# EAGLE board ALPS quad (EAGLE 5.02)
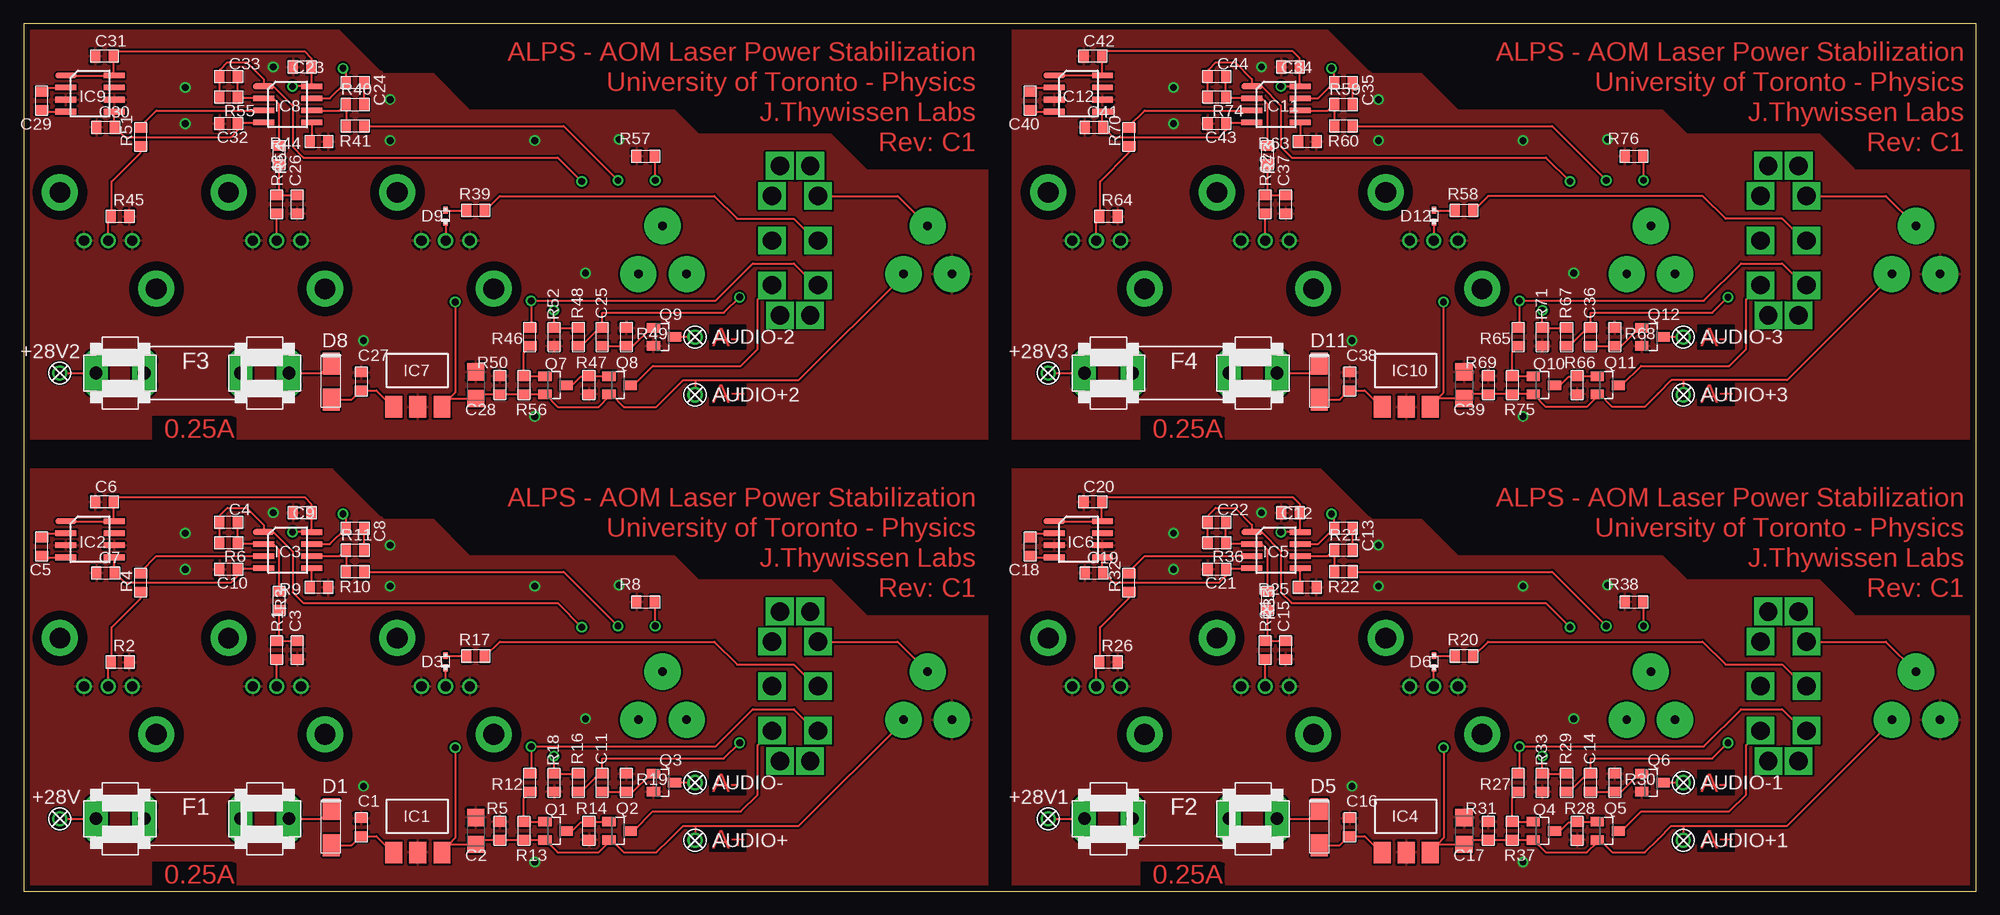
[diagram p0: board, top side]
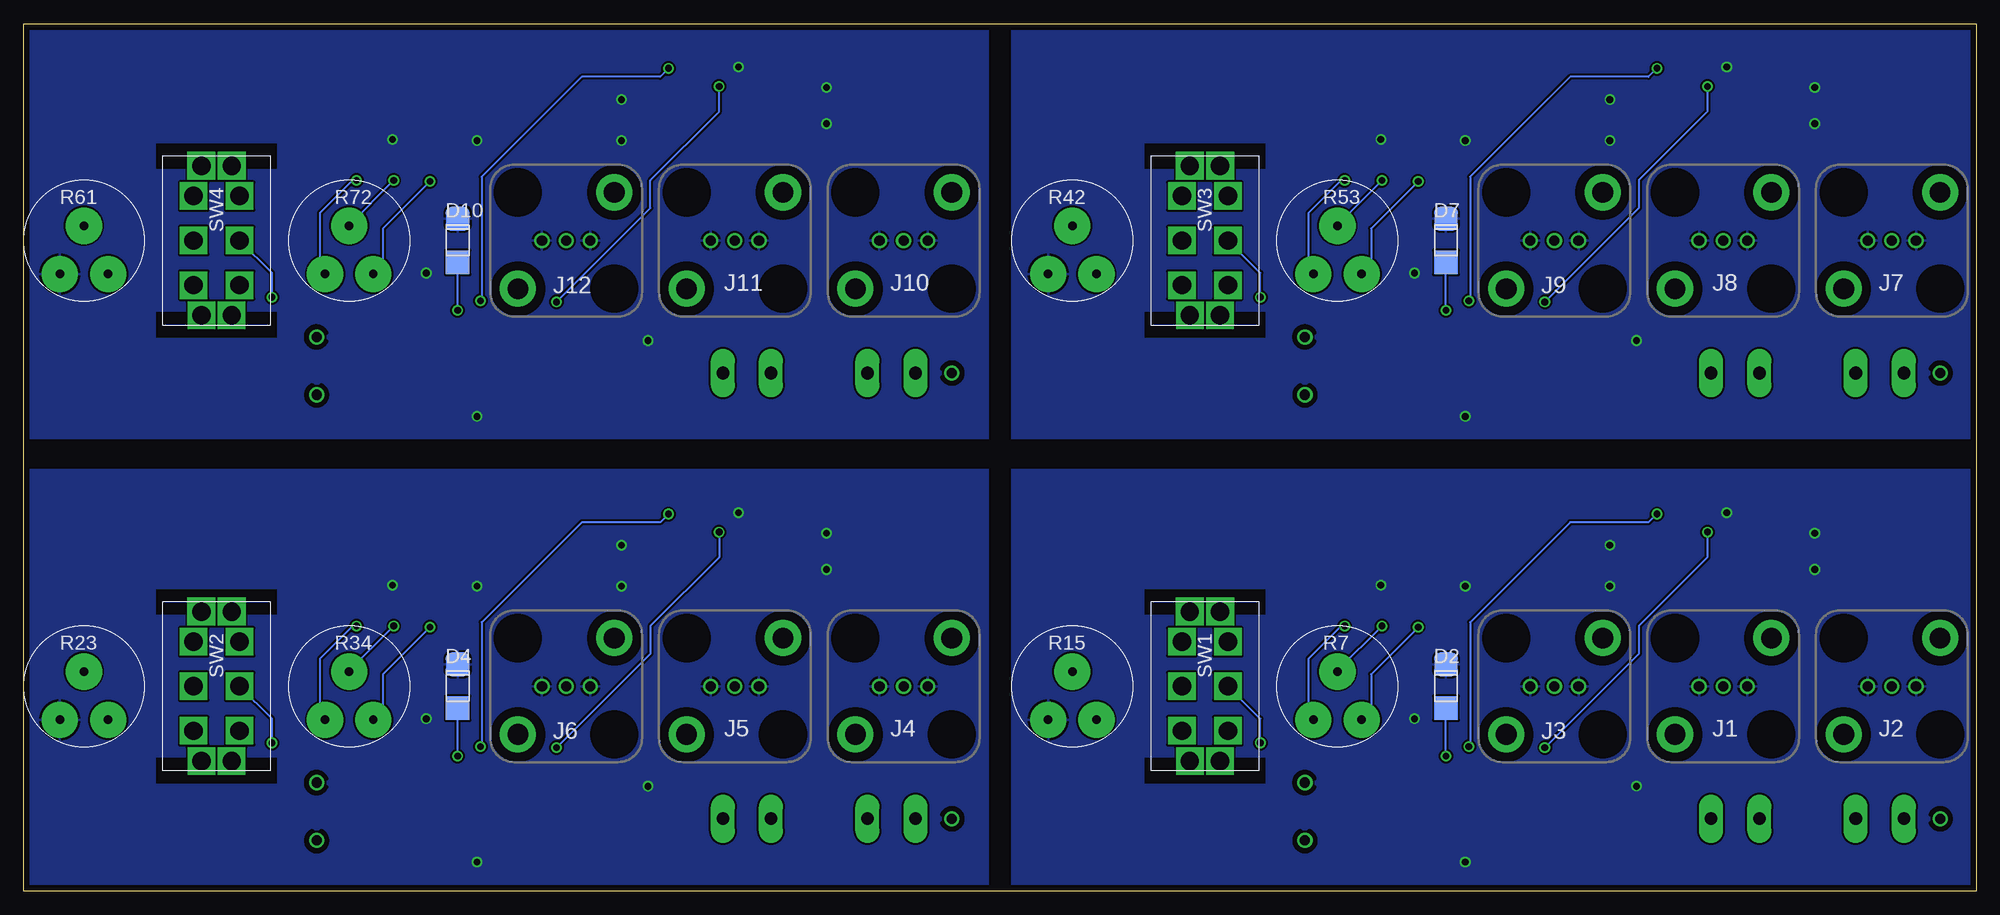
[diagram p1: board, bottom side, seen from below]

Size 205.74 x 91.44 mm. Coordinates in mm from the lower left corner, seen from the top.
Outline: 0,0 205.74,0 205.74,91.44 0,91.44 0,0
Copper layers (1*16): Top 0.035mm / dielectric 1.5mm / Bottom 0.035mm
Design rules "DRC standard check (8mil trace and gap, 20mil drill, etc) *": minimum track width 7mil, minimum drill 20mil, track to track 7mil, track to pad 7mil, pad to pad 7mil, via to via 7mil, smd to smd 7mil, copper to edge 25mil, drill to drill 8mil, minimum pad ring 10mil, minimum via ring 8mil, stop-mask expansion 4mil, vias tented up to drill 0mil, thermal gap 10mil
Net classes: 0 default: width 0.203 mm, clearance 0.203 mm
tRestrict: 73 lines
bRestrict: 1 lines

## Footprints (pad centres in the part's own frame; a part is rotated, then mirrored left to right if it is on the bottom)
TP-0.042B = drill 1.067 round: TP 0,0
2012(0805) = smd 1.016 x 1.397: 1 -0.953,0; 2 0.953,0
3216(1206) = smd 1.8 x 1.8: 1 -1.4,0; 2 1.4,0
EIA-A(SMA) = smd 2.3 x 1.8: 1A -1.905,0; 2K 1.905,0
1209 = smd 2.5 x 2.5: A 2.3,0; K -2.3,0
SOD523 = smd 0.7 x 0.5: A 0.67,0; C -0.6,0
FUSE = drill 1.321 pad 2.54 long: 1A -10.16,0; 1B -5.08,0; 2A 10.16,0; 2B 5.08,0
SOT223 = smd 1.778 x 2.286: 1 -2.54,-2.54; 2@1 0,-2.54; 3 2.54,-2.54
SOIC-8 = smd 0.6 x 2.2: 1 -1.27,-2.54; 2 0,-2.54; 3 1.27,-2.54; 4 2.54,-2.54; 5 2.54,2.54; 6 1.27,2.54; 7 0,2.54; 8 -1.27,2.54
CONN-BNC-AMP-TYPE1VERT = drill 1.067 round: CONDUCTOR 0,0; SHIELD1 -2.54,0; SHIELD2 2.54,0 | drill 2.184 pad 3.81 round: MTG1 -5.08,-5.08; MTG2 5.08,5.08
SOT23 = smd 1 x 1.4: 1 -0.953,-0.953; 2 0.953,-0.953; 3 0,1.27
PRECISION-SPR-RV8(POT) = drill 0.889 pad 3.81 round: CCW -2.54,-3.531; CW 2.54,-3.531; W 0,1.549
SWITCH-ESWITCH_100DP?VS2 = drill 1.93 square: C1 -2.42,0; C2 2.42,0; MTG3 1.595,-7.875; MTG4 -1.595,-7.875; NC1 -2.42,-4.7; NC2 2.42,-4.7; NO1 -2.42,4.7; NO2 2.42,4.7 | drill 1.93 pad 2.946 square: MTG1 -1.595,7.875; MTG2 1.595,7.875

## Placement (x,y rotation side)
+28V  Keystone 5002  [TP-0.042B]  3.81,7.62 180 top
+28V1  Keystone 5002  [TP-0.042B]  107.95,7.62 180 top
+28V2  Keystone 5002  [TP-0.042B]  3.81,54.61 180 top
+28V3  Keystone 5002  [TP-0.042B]  107.95,54.61 180 top
AUD  "Unlocked"  [MISC]  not placed on the board
AUDIO+  Keystone 5002  [TP-0.042B]  70.74,5.33 270 top
AUDIO+1  Keystone 5002  [TP-0.042B]  174.88,5.33 270 top
AUDIO+2  Keystone 5002  [TP-0.042B]  70.74,52.32 270 top
AUDIO+3  Keystone 5002  [TP-0.042B]  174.88,52.32 270 top
AUDIO-  Keystone 5002  [TP-0.042B]  70.74,11.43 0 top
AUDIO-1  Keystone 5002  [TP-0.042B]  174.88,11.43 0 top
AUDIO-2  Keystone 5002  [TP-0.042B]  70.74,58.42 0 top
AUDIO-3  Keystone 5002  [TP-0.042B]  174.88,58.42 0 top
C1  0.1uF  [2012(0805)]  35.56,6.73 270 top
C2  10uF  [3216(1206)]  47.62,6.35 270 top
C3  2.2nF  [2012(0805)]  28.83,25.4 90 top
C4  100pF  [2012(0805)]  21.59,38.86 180 top
C5  10uF  [2012(0805)]  1.91,36.32 90 top
C6  0.1uF  [2012(0805)]  8.51,41.02 180 top
C7  10uF  [2012(0805)]  8.64,33.53 0 top
C8  100pF  [2012(0805)]  34.92,38.23 180 top
C9  0.1uF  [2012(0805)]  29.34,39.88 180 top
C10  0.1uF  [2012(0805)]  21.59,33.91 180 top
C11  3.3uF  [2012(0805)]  60.96,11.43 90 top
C12  0.1uF  [2012(0805)]  133.48,39.88 180 top
C13  100pF  [2012(0805)]  139.06,38.23 180 top
C14  3.3uF  [2012(0805)]  165.1,11.43 90 top
C15  2.2nF  [2012(0805)]  132.97,25.4 90 top
C16  0.1uF  [2012(0805)]  139.7,6.73 270 top
C17  10uF  [3216(1206)]  151.76,6.35 270 top
C18  10uF  [2012(0805)]  106.05,36.32 90 top
C19  10uF  [2012(0805)]  112.78,33.53 0 top
C20  0.1uF  [2012(0805)]  112.65,41.02 180 top
C21  0.1uF  [2012(0805)]  125.73,33.91 180 top
C22  100pF  [2012(0805)]  125.73,38.86 180 top
C23  0.1uF  [2012(0805)]  29.34,86.87 180 top
C24  100pF  [2012(0805)]  34.92,85.22 180 top
C25  3.3uF  [2012(0805)]  60.96,58.42 90 top
C26  2.2nF  [2012(0805)]  28.83,72.39 90 top
C27  0.1uF  [2012(0805)]  35.56,53.72 270 top
C28  10uF  [3216(1206)]  47.62,53.34 270 top
C29  10uF  [2012(0805)]  1.91,83.31 90 top
C30  10uF  [2012(0805)]  8.64,80.52 0 top
C31  0.1uF  [2012(0805)]  8.51,88.01 180 top
C32  0.1uF  [2012(0805)]  21.59,80.9 180 top
C33  100pF  [2012(0805)]  21.59,85.85 180 top
C34  0.1uF  [2012(0805)]  133.48,86.87 180 top
C35  100pF  [2012(0805)]  139.06,85.22 180 top
C36  3.3uF  [2012(0805)]  165.1,58.42 90 top
C37  2.2nF  [2012(0805)]  132.97,72.39 90 top
C38  0.1uF  [2012(0805)]  139.7,53.72 270 top
C39  10uF  [3216(1206)]  151.76,53.34 270 top
C40  10uF  [2012(0805)]  106.05,83.31 90 top
C41  10uF  [2012(0805)]  112.78,80.52 0 top
C42  0.1uF  [2012(0805)]  112.65,88.01 180 top
C43  0.1uF  [2012(0805)]  125.73,80.9 180 top
C44  100pF  [2012(0805)]  125.73,85.85 180 top
CASE1  1590CFL  [MISC]  not placed on the board
D1  SMAZ16-13-F  [EIA-A(SMA)]  32.38,6.73 90 top
D2  Red  [1209]  55.88,21.59 270 bottom
D3  ZHCS350TA  [SOD523]  44.45,24.13 90 top
D4  Red  [1209]  160.02,21.59 270 bottom
D5  SMAZ16-13-F  [EIA-A(SMA)]  136.53,6.73 90 top
D6  ZHCS350TA  [SOD523]  148.59,24.13 90 top
D7  Red  [1209]  55.88,68.58 270 bottom
D8  SMAZ16-13-F  [EIA-A(SMA)]  32.38,53.72 90 top
D9  ZHCS350TA  [SOD523]  44.45,71.12 90 top
D10  Red  [1209]  160.02,68.58 270 bottom
D11  SMAZ16-13-F  [EIA-A(SMA)]  136.53,53.72 90 top
D12  ZHCS350TA  [SOD523]  148.59,71.12 90 top
F1  0.25A  [FUSE]  17.78,7.62 0 top
F2  0.25A  [FUSE]  121.92,7.62 0 top
F3  0.25A  [FUSE]  17.78,54.61 0 top
F4  0.25A  [FUSE]  121.92,54.61 0 top
IC1  MIC2920A-5.0WS  [SOT223]  41.53,6.6 0 top
IC2  LM2662M  [SOIC-8]  6.99,37.72 270 top
IC3  AD8032AR(z)  [SOIC-8]  27.81,36.58 270 top
IC4  MIC2920A-5.0WS  [SOT223]  145.67,6.6 0 top
IC5  AD8032AR(z)  [SOIC-8]  131.95,36.58 270 top
IC6  LM2662M  [SOIC-8]  111.12,37.72 270 top
IC7  MIC2920A-5.0WS  [SOT223]  41.53,53.59 0 top
IC8  AD8032AR(z)  [SOIC-8]  27.81,83.57 270 top
IC9  LM2662M  [SOIC-8]  6.99,84.71 270 top
IC10  MIC2920A-5.0WS  [SOT223]  145.67,53.59 0 top
IC11  AD8032AR(z)  [SOIC-8]  131.95,83.57 270 top
IC12  LM2662M  [SOIC-8]  111.12,84.71 270 top
J1  5227222-6  [CONN-BNC-AMP-TYPE1VERT]  26.67,21.59 0 bottom
J2  5227222-6  [CONN-BNC-AMP-TYPE1VERT]  8.89,21.59 0 bottom
J3  5227222-6  [CONN-BNC-AMP-TYPE1VERT]  44.45,21.59 0 bottom
J4  5227222-6  [CONN-BNC-AMP-TYPE1VERT]  113.03,21.59 0 bottom
J5  5227222-6  [CONN-BNC-AMP-TYPE1VERT]  130.81,21.59 0 bottom
J6  5227222-6  [CONN-BNC-AMP-TYPE1VERT]  148.59,21.59 0 bottom
J7  5227222-6  [CONN-BNC-AMP-TYPE1VERT]  8.89,68.58 0 bottom
J8  5227222-6  [CONN-BNC-AMP-TYPE1VERT]  26.67,68.58 0 bottom
J9  5227222-6  [CONN-BNC-AMP-TYPE1VERT]  44.45,68.58 0 bottom
J10  5227222-6  [CONN-BNC-AMP-TYPE1VERT]  113.03,68.58 0 bottom
J11  5227222-6  [CONN-BNC-AMP-TYPE1VERT]  130.81,68.58 0 bottom
J12  5227222-6  [CONN-BNC-AMP-TYPE1VERT]  148.59,68.58 0 bottom
KNOB1  OESA-50-4-6  [MISC]  not placed on the board
KNOB2  OESA-50-4-6  [MISC]  not placed on the board
LIGHTPIPE1  PLP2-500  [MISC]  not placed on the board
NUT1  1-329631-2  [MISC]  not placed on the board
NUT2  1-329631-2  [MISC]  not placed on the board
NUT3  1-329631-2  [MISC]  not placed on the board
Q1  MMBT3906  [SOT23]  55.88,6.35 270 top
Q2  MMBT3906  [SOT23]  62.61,6.35 270 top
Q3  2N7002TA  [SOT23]  67.31,11.43 270 top
Q4  MMBT3906  [SOT23]  160.02,6.35 270 top
Q5  MMBT3906  [SOT23]  166.75,6.35 270 top
Q6  2N7002TA  [SOT23]  171.45,11.43 270 top
Q7  MMBT3906  [SOT23]  55.88,53.34 270 top
Q8  MMBT3906  [SOT23]  62.61,53.34 270 top
Q9  2N7002TA  [SOT23]  67.31,58.42 270 top
Q10  MMBT3906  [SOT23]  160.02,53.34 270 top
Q11  MMBT3906  [SOT23]  166.75,53.34 270 top
Q12  2N7002TA  [SOT23]  171.45,58.42 270 top
R1  2K  [2012(0805)]  26.67,25.4 90 top
R2  49.9  [2012(0805)]  10.16,24.13 180 top
R3  1K  [2012(0805)]  26.92,30.61 90 top
R4  1K  [2012(0805)]  12.32,32.51 90 top
R5  2K  [2012(0805)]  50.16,6.35 270 top
R6  1K  [2012(0805)]  21.59,36.7 180 top
R7  1K  [PRECISION-SPR-RV8(POT)]  67.31,21.59 0 bottom
R8  49.9  [2012(0805)]  65.53,30.48 0 top
R9  1K  [2012(0805)]  31.11,32 180 top
R10  1K  [2012(0805)]  34.92,33.66 180 top
R11  0  [2012(0805)]  34.92,35.94 0 top
R12  10K  [2012(0805)]  53.34,11.43 90 top
R13  20K  [2012(0805)]  52.7,6.35 270 top
R14  10K  [2012(0805)]  59.56,6.35 90 top
R15  1K  [PRECISION-SPR-RV8(POT)]  95.25,21.59 0 bottom
R16  1K  [2012(0805)]  58.42,11.43 270 top
R17  150  [2012(0805)]  47.62,24.77 180 top
R18  10K  [2012(0805)]  55.88,11.43 90 top
R19  1M  [2012(0805)]  63.5,11.43 270 top
R20  150  [2012(0805)]  151.76,24.77 180 top
R21  0  [2012(0805)]  139.06,35.94 0 top
R22  1K  [2012(0805)]  139.06,33.66 180 top
R23  1K  [PRECISION-SPR-RV8(POT)]  199.39,21.59 0 bottom
R24  2K  [2012(0805)]  130.81,25.4 90 top
R25  1K  [2012(0805)]  135.25,32 180 top
R26  49.9  [2012(0805)]  114.3,24.13 180 top
R27  10K  [2012(0805)]  157.48,11.43 90 top
R28  10K  [2012(0805)]  163.7,6.35 90 top
R29  1K  [2012(0805)]  162.56,11.43 270 top
R30  1M  [2012(0805)]  167.64,11.43 270 top
R31  2K  [2012(0805)]  154.31,6.35 270 top
R32  1K  [2012(0805)]  116.46,32.51 90 top
R33  10K  [2012(0805)]  160.02,11.43 90 top
R34  1K  [PRECISION-SPR-RV8(POT)]  171.45,21.59 0 bottom
R35  1K  [2012(0805)]  131.06,30.61 90 top
R36  1K  [2012(0805)]  125.73,36.7 180 top
R37  20K  [2012(0805)]  156.84,6.35 270 top
R38  49.9  [2012(0805)]  169.67,30.48 0 top
R39  150  [2012(0805)]  47.62,71.75 180 top
R40  0  [2012(0805)]  34.92,82.93 0 top
R41  1K  [2012(0805)]  34.92,80.64 180 top
R42  1K  [PRECISION-SPR-RV8(POT)]  95.25,68.58 0 bottom
R43  2K  [2012(0805)]  26.67,72.39 90 top
R44  1K  [2012(0805)]  31.11,78.99 180 top
R45  49.9  [2012(0805)]  10.16,71.12 180 top
R46  10K  [2012(0805)]  53.34,58.42 90 top
R47  10K  [2012(0805)]  59.56,53.34 90 top
R48  1K  [2012(0805)]  58.42,58.42 270 top
R49  1M  [2012(0805)]  63.5,58.42 270 top
R50  2K  [2012(0805)]  50.16,53.34 270 top
R51  1K  [2012(0805)]  12.32,79.5 90 top
R52  10K  [2012(0805)]  55.88,58.42 90 top
R53  1K  [PRECISION-SPR-RV8(POT)]  67.31,68.58 0 bottom
R54  1K  [2012(0805)]  26.92,77.6 90 top
R55  1K  [2012(0805)]  21.59,83.69 180 top
R56  20K  [2012(0805)]  52.7,53.34 270 top
R57  49.9  [2012(0805)]  65.53,77.47 0 top
R58  150  [2012(0805)]  151.76,71.75 180 top
R59  0  [2012(0805)]  139.06,82.93 0 top
R60  1K  [2012(0805)]  139.06,80.64 180 top
R61  1K  [PRECISION-SPR-RV8(POT)]  199.39,68.58 0 bottom
R62  2K  [2012(0805)]  130.81,72.39 90 top
R63  1K  [2012(0805)]  135.25,78.99 180 top
R64  49.9  [2012(0805)]  114.3,71.12 180 top
R65  10K  [2012(0805)]  157.48,58.42 90 top
R66  10K  [2012(0805)]  163.7,53.34 90 top
R67  1K  [2012(0805)]  162.56,58.42 270 top
R68  1M  [2012(0805)]  167.64,58.42 270 top
R69  2K  [2012(0805)]  154.31,53.34 270 top
R70  1K  [2012(0805)]  116.46,79.5 90 top
R71  10K  [2012(0805)]  160.02,58.42 90 top
R72  1K  [PRECISION-SPR-RV8(POT)]  171.45,68.58 0 bottom
R73  1K  [2012(0805)]  131.06,77.6 90 top
R74  1K  [2012(0805)]  125.73,83.69 180 top
R75  20K  [2012(0805)]  156.84,53.34 270 top
R76  49.9  [2012(0805)]  169.67,77.47 0 top
SW1  100DP3T2B4VS2RE  [SWITCH-ESWITCH_100DP?VS2]  81.28,21.59 0 bottom
SW2  100DP3T2B4VS2RE  [SWITCH-ESWITCH_100DP?VS2]  185.42,21.59 0 bottom
SW3  100DP3T2B4VS2RE  [SWITCH-ESWITCH_100DP?VS2]  81.28,68.58 0 bottom
SW4  100DP3T2B4VS2RE  [SWITCH-ESWITCH_100DP?VS2]  185.42,68.58 0 bottom
U$18  [TITLEBLOCK_PCB]  not placed on the board
WASH1  1-329632-2  [MISC]  not placed on the board
WASH2  1-329632-2  [MISC]  not placed on the board
WASH3  1-329632-2  [MISC]  not placed on the board

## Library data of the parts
+28V +28V1-+28V3 AUDIO+ AUDIO+1-AUDIO+3 AUDIO- AUDIO-1-AUDIO-3 C1 C3 C4 C6 C8-C10 C12 C13 C15 C16 C20-C24 C26 C27 C31-C35 C37 C38 C42-C44 IC2 IC3 IC5 IC6 IC8 IC9 IC11 IC12 Q1 Q2 Q4 Q5 Q7 Q8 Q10 Q11 R1-R6 R8-R14 R16-R22 R24-R33 R35-R41 R43-R52 R54-R60 R62-R71 R73-R76 U$18 WASH1-WASH3 = QuantumOptics
AUD = QuantumOptics; MFG: Mallory; PN: MSR516WR
C2 C17 C28 C39 = QuantumOptics; MFG: Nichicon; PN: F951C106MSAAQ2
C5 C7 C18 C19 C29 C30 C40 C41 = QuantumOptics; DESC: Low ESR; MFG: AVX; PN: TCJR106M006R0500
C11 C14 C25 C36 = QuantumOptics; MFG: Yageo; PN: CC0805ZKY5V6BB335
CASE1 = QuantumOptics; MFG: Hammond
D1 D5 D8 D11 = QuantumOptics; MFG: Diodes Inc; RATING: 10V/1W
D2 D4 D7 D10 = QuantumOptics; DESC: "Unlocked"; MFG: Lumex; PN: SML-LXL1209SIC
D3 D6 D9 D12 = QuantumOptics; MFG: Zetex
F1-F4 = QuantumOptics; MFG: Littlefuse; PN: 100056
IC1 IC4 IC7 IC10 = QuantumOptics; MFG: Micrel
J1 J3 J5 J6 J8 J9 J11 J12 = QuantumOptics; DESC: "PD Input"; MFG: Amp
J2 J4 J7 J10 = QuantumOptics; DESC: "PD In"; MFG: Amp
KNOB1 KNOB2 = QuantumOptics; MFG: Kilo Int'l
LIGHTPIPE1 = QuantumOptics; MFG: Bivar inc.
NUT1-NUT3 = QuantumOptics; MFG: Amp
Q3 Q6 Q9 Q12 = QuantumOptics; MFG: Zetex; PKG: SOT23
R7 R34 R53 R72 = QuantumOptics; DESC: "Gain"; MFG: Precision Elec.; PN: SPRU1031S28
R15 R23 R42 R61 = QuantumOptics; MFG: Precision Electronics Components; PN: SPRU1021S28
SW1-SW4 = QuantumOptics; ALTPN: (Alt: 100DP1T1B1M2REH); DESC: "Man/Auto"; MFG: E-Switch

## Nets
+5V: AUDIO+.TP C2.2 C6.1 C9.1 IC1.3 IC2.1 IC2.8 IC3.8 Q1.2 Q2.2 R5.2 R13.2 R15.CW
+5V1: AUDIO+1.TP C12.1 C17.2 C20.1 IC4.3 IC5.8 IC6.1 IC6.8 Q4.2 Q5.2 R23.CW R31.2 R37.2
+5V2: AUDIO+2.TP C23.1 C28.2 C31.1 IC7.3 IC8.8 IC9.1 IC9.8 Q7.2 Q8.2 R42.CW R50.2 R56.2
+5V3: AUDIO+3.TP C34.1 C39.2 C42.1 IC10.3 IC11.8 IC12.1 IC12.8 Q10.2 Q11.2 R61.CW R69.2 R75.2
-5V: C7.2 C10.1 IC2.5 IC3.4
-5V1: C19.2 C21.1 IC5.4 IC6.5
-5V2: C30.2 C32.1 IC8.4 IC9.5
-5V3: C41.2 C43.1 IC11.4 IC12.5
AGND: C1.1 C2.1 C3.1 C6.2 C7.1 C9.2 C10.2 D2.K IC1.2@1 IC2.3 IC2.6 J1.SHIELD1 J1.SHIELD2 J2.SHIELD1 J2.SHIELD2 J3.SHIELD1 J3.SHIELD2 Q3.2 R2.1 R5.1 R8.1 R9.1 R14.1 R15.CCW R18.1 R19.1
AGND1: C12.2 C15.1 C16.1 C17.1 C19.1 C20.2 C21.2 D4.K IC4.2@1 IC6.3 IC6.6 J4.SHIELD1 J4.SHIELD2 J5.SHIELD1 J5.SHIELD2 J6.SHIELD1 J6.SHIELD2 Q6.2 R23.CCW R25.1 R26.1 R28.1 R30.1 R31.1 R33.1 R38.1
AGND2: C23.2 C26.1 C27.1 C28.1 C30.1 C31.2 C32.2 D7.K IC7.2@1 IC9.3 IC9.6 J7.SHIELD1 J7.SHIELD2 J8.SHIELD1 J8.SHIELD2 J9.SHIELD1 J9.SHIELD2 Q9.2 R42.CCW R44.1 R45.1 R47.1 R49.1 R50.1 R52.1 R57.1
AGND3: C34.2 C37.1 C38.1 C39.1 C41.1 C42.2 C43.2 D10.K IC10.2@1 IC12.3 IC12.6 J10.SHIELD1 J10.SHIELD2 J11.SHIELD1 J11.SHIELD2 J12.SHIELD1 J12.SHIELD2 Q12.2 R61.CCW R63.1 R64.1 R66.1 R68.1 R69.1 R71.1 R76.1
N$1: D3.C J3.CONDUCTOR
N$2: D6.C J6.CONDUCTOR
N$3: IC3.6 R10.2 R11.1
N$4: C8.1 R11.2
N$5: R17.1 SW1.C1
N$6: R15.W SW1.NO1
N$7: J1.CONDUCTOR R1.1
N$8: IC3.5 R9.2
N$9: Q1.3 Q2.1 R14.2
N$10: J2.CONDUCTOR R2.2 R4.1
N$11: Q1.1 R12.1 R13.1
N$12: C11.2 R16.2 SW1.C2
N$13: D2.A R16.1 R18.2
N$14: Q2.3 SW1.NC2
N$15: C11.1 Q3.1 R19.2
N$16: AUDIO-.TP Q3.3
N$17: C1.2 D1.1A IC1.1
N$18: C5.2 IC2.2
N$19: +28V.TP F1.1A
N$20: D1.2K F1.2A
N$21: C4.2 IC3.1 R6.2 R7.CW
N$22: C4.1 IC3.2 R3.2 R6.1
N$23: IC3.3 R4.2
N$24: R7.W R10.1
N$25: R7.CCW R8.2
N$26: C5.1 IC2.4
N$27: C3.2 R1.2 R3.1
N$28: D3.A R17.2
N$29: C8.2 IC3.7 R12.2 SW1.NC1
N$30: IC5.6 R21.1 R22.2
N$31: C13.1 R21.2
N$32: R20.1 SW2.C1
N$33: R23.W SW2.NO1
N$34: J5.CONDUCTOR R24.1
N$35: IC5.5 R25.2
N$36: J4.CONDUCTOR R26.2 R32.1
N$37: Q4.3 Q5.1 R28.2
N$38: Q4.1 R27.1 R37.1
N$39: C14.2 R29.2 SW2.C2
N$40: D4.A R29.1 R33.2
N$41: C14.1 Q6.1 R30.2
N$42: C16.2 D5.1A IC4.1
N$43: D5.2K F2.2A
N$44: +28V1.TP F2.1A
N$45: Q5.3 SW2.NC2
N$46: AUDIO-1.TP Q6.3
N$47: C18.2 IC6.2
N$48: C18.1 IC6.4
N$49: C15.2 R24.2 R35.1
N$50: C22.2 IC5.1 R34.CW R36.2
N$51: C22.1 IC5.2 R35.2 R36.1
N$52: D6.A R20.2
N$53: IC5.3 R32.2
N$54: R22.1 R34.W
N$55: R34.CCW R38.2
N$56: C13.2 IC5.7 R27.2 SW2.NC1
N$57: D9.C J9.CONDUCTOR
N$58: IC8.6 R40.1 R41.2
N$59: C24.1 R40.2
N$60: R39.1 SW3.C1
N$61: R42.W SW3.NO1
N$62: J8.CONDUCTOR R43.1
N$63: IC8.5 R44.2
N$64: J7.CONDUCTOR R45.2 R51.1
N$65: Q7.3 Q8.1 R47.2
N$66: Q7.1 R46.1 R56.1
N$67: C25.2 R48.2 SW3.C2
N$68: D7.A R48.1 R52.2
N$69: C25.1 Q9.1 R49.2
N$70: C27.2 D8.1A IC7.1
N$71: D8.2K F3.2A
N$72: +28V2.TP F3.1A
N$73: Q8.3 SW3.NC2
N$74: AUDIO-2.TP Q9.3
N$75: C29.2 IC9.2
N$76: C29.1 IC9.4
N$77: C26.2 R43.2 R54.1
N$78: C33.2 IC8.1 R53.CW R55.2
N$79: C33.1 IC8.2 R54.2 R55.1
N$80: D9.A R39.2
N$81: IC8.3 R51.2
N$82: R41.1 R53.W
N$83: R53.CCW R57.2
N$84: C24.2 IC8.7 R46.2 SW3.NC1
N$85: D12.C J12.CONDUCTOR
N$86: IC11.6 R59.1 R60.2
N$87: C35.1 R59.2
N$88: R58.1 SW4.C1
N$89: R61.W SW4.NO1
N$90: J11.CONDUCTOR R62.1
N$91: IC11.5 R63.2
N$92: J10.CONDUCTOR R64.2 R70.1
N$93: Q10.3 Q11.1 R66.2
N$94: Q10.1 R65.1 R75.1
N$95: C36.2 R67.2 SW4.C2
N$96: D10.A R67.1 R71.2
N$97: C36.1 Q12.1 R68.2
N$98: C38.2 D11.1A IC10.1
N$99: D11.2K F4.2A
N$100: +28V3.TP F4.1A
N$101: Q11.3 SW4.NC2
N$102: AUDIO-3.TP Q12.3
N$103: C40.2 IC12.2
N$104: C40.1 IC12.4
N$105: C37.2 R62.2 R73.1
N$106: C44.2 IC11.1 R72.CW R74.2
N$107: C44.1 IC11.2 R73.2 R74.1
N$108: D12.A R58.2
N$109: IC11.3 R70.2
N$110: R60.1 R72.W
N$111: R72.CCW R76.2
N$112: C35.2 IC11.7 R65.2 SW4.NC1

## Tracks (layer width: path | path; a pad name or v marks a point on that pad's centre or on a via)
+5V  (via drill 0.71)
  Top 0.203: IC2.1 IC2.8 9.53,38.86 9.46,38.92 C6.1 9.46,41.15 9.53,41.15 9.91,41.53 29.59,41.53 30.29,40.83 C9.1 30.29,38.16 30.35,38.1 IC3.8 v28.32,37.85 | IC1.3 44.07,4.19 44.83,4.95 | 44.83,4.95 45.47,5.59 v45.47,15.11 | R15.CW 92.71,17.91 81.66,6.86 70.74,6.86 | 70.74,6.86 AUDIO+.TP | 68.07,5.46 68.01,5.4 | 68.07,5.46 69.47,6.86 70.74,6.86 | 44.83,4.95 C2.2 48.07,5.4 R5.2 50.16,5.46 50.23,5.4 R13.2 52.7,5.46 52.77,5.4 Q1.2 54.93,5.46 54.99,5.33 56.26,4.06 60.58,4.06 61.66,5.14 Q2.2 61.91,5.4 63.25,4.06 66.67,4.06 68.07,5.46
  Bottom 0.203: v45.47,15.11 35.56,25.02 35.56,27.94 28.32,35.18 v28.32,37.85
+5V1  (via drill 0.71)
  Top 0.203: IC6.1 IC6.8 113.67,38.86 113.6,38.92 C20.1 113.6,41.15 113.67,41.15 114.05,41.53 133.73,41.53 134.43,40.83 C12.1 134.43,38.16 134.49,38.1 IC5.8 v132.46,37.85 | IC4.3 148.21,4.19 148.97,4.95 | 148.97,4.95 149.61,5.59 v149.61,15.11 | R23.CW 196.85,17.91 185.8,6.86 174.88,6.86 | 174.88,6.86 AUDIO+1.TP | 172.21,5.46 172.15,5.4 | 172.21,5.46 173.61,6.86 174.88,6.86 | 148.97,4.95 C17.2 152.21,5.4 R31.2 154.31,5.46 154.37,5.4 R37.2 156.84,5.46 156.91,5.4 Q4.2 159.07,5.46 159.13,5.33 160.4,4.06 164.72,4.06 165.8,5.14 Q5.2 166.05,5.4 167.39,4.06 170.81,4.06 172.21,5.46
  Bottom 0.203: v149.61,15.11 139.7,25.02 139.7,27.94 132.46,35.18 v132.46,37.85
+5V2  (via drill 0.71)
  Top 0.203: IC9.1 IC9.8 9.53,85.85 9.46,85.92 C31.1 9.46,88.14 9.53,88.14 9.91,88.52 29.59,88.52 30.29,87.82 C23.1 30.29,85.15 30.35,85.09 IC8.8 v28.32,84.84 | IC7.3 44.07,51.18 44.83,51.94 | 44.83,51.94 45.47,52.58 v45.47,62.1 | R42.CW 92.71,64.9 81.66,53.85 70.74,53.85 | 70.74,53.85 AUDIO+2.TP | 68.07,52.45 68.01,52.39 | 68.07,52.45 69.47,53.85 70.74,53.85 | 44.83,51.94 C28.2 48.07,52.39 R50.2 50.16,52.45 50.23,52.39 R56.2 52.7,52.45 52.77,52.39 Q7.2 54.93,52.45 54.99,52.32 56.26,51.05 60.58,51.05 61.66,52.13 Q8.2 61.91,52.39 63.25,51.05 66.67,51.05 68.07,52.45
  Bottom 0.203: v45.47,62.1 35.56,72.01 35.56,74.93 28.32,82.17 v28.32,84.84
+5V3  (via drill 0.71)
  Top 0.203: IC12.1 IC12.8 113.67,85.85 113.6,85.92 C42.1 113.6,88.14 113.67,88.14 114.05,88.52 133.73,88.52 134.43,87.82 C34.1 134.43,85.15 134.49,85.09 IC11.8 v132.46,84.84 | IC10.3 148.21,51.18 148.97,51.94 | 148.97,51.94 149.61,52.58 v149.61,62.1 | R61.CW 196.85,64.9 185.8,53.85 174.88,53.85 | 174.88,53.85 AUDIO+3.TP | 172.21,52.45 172.15,52.39 | 172.21,52.45 173.61,53.85 174.88,53.85 | 148.97,51.94 C39.2 152.21,52.39 R69.2 154.31,52.45 154.37,52.39 R75.2 156.84,52.45 156.91,52.39 Q10.2 159.07,52.45 159.13,52.32 160.4,51.05 164.72,51.05 165.8,52.13 Q11.2 166.05,52.39 167.39,51.05 170.81,51.05 172.21,52.45
  Bottom 0.203: v149.61,62.1 139.7,72.01 139.7,74.93 132.46,82.17 v132.46,84.84
-5V
  Top 0.203: IC2.5 9.53,33.66 9.59,33.66 C7.2 9.65,33.53 10.67,32.51 21.84,32.51 22.54,33.21 C10.1 22.48,33.91 22.61,34.04 IC3.4
-5V1
  Top 0.203: IC6.5 113.67,33.66 113.73,33.66 C19.2 113.79,33.53 114.81,32.51 125.98,32.51 126.68,33.21 C21.1 126.62,33.91 126.75,34.04 IC5.4
-5V2
  Top 0.203: IC9.5 9.53,80.64 9.59,80.64 C30.2 9.65,80.52 10.67,79.5 21.84,79.5 22.54,80.2 C32.1 22.48,80.9 22.61,81.03 IC8.4
-5V3
  Top 0.203: IC12.5 113.67,80.64 113.73,80.64 C41.2 113.79,80.52 114.81,79.5 125.98,79.5 126.68,80.2 C43.1 126.62,80.9 126.75,81.03 IC11.4
AGND  (via drill 0.71)
  other vias: 17.02,33.91 17.02,37.72 38.61,36.45 38.61,32.13 53.85,32.13 59.18,18.16 62.74,32.26 35.81,11.05 53.85,3.05 26.29,39.88
  pour Top: 0,0 101.6,0 101.6,29.21 88.9,29.21 85.09,33.02 71.12,33.02 68.58,35.56 46.99,35.56 43.18,39.37 37.59,39.37 32.51,44.45 0,44.45
  pour Bottom: 0,0 101.6,0 101.6,44.45 0,44.45
AGND1  (via drill 0.71)
  other vias: 121.16,33.91 121.16,37.72 142.75,36.45 142.75,32.13 157.99,32.13 163.32,18.16 166.88,32.26 139.95,11.05 157.99,3.05 130.43,39.88
  pour Top: 104.14,0 205.74,0 205.74,29.21 193.04,29.21 189.23,33.02 175.26,33.02 172.72,35.56 151.13,35.56 147.32,39.37 141.73,39.37 136.65,44.45 104.14,44.45
  pour Bottom: 104.14,0 205.74,0 205.74,44.45 104.14,44.45
AGND2  (via drill 0.71)
  other vias: 17.02,80.9 17.02,84.71 38.61,83.44 38.61,79.12 53.85,79.12 59.18,65.15 62.74,79.25 35.81,58.04 53.85,50.04 26.29,86.87
  pour Top: 0,46.99 101.6,46.99 101.6,76.2 88.9,76.2 85.09,80.01 71.12,80.01 68.58,82.55 46.99,82.55 43.18,86.36 37.59,86.36 32.51,91.44 0,91.44
  pour Bottom: 0,46.99 101.6,46.99 101.6,91.44 0,91.44
AGND3  (via drill 0.71)
  other vias: 121.16,80.9 121.16,84.71 142.75,83.44 142.75,79.12 157.99,79.12 163.32,65.15 166.88,79.25 139.95,58.04 157.99,50.04 130.43,86.87
  pour Top: 104.14,46.99 205.74,46.99 205.74,76.2 193.04,76.2 189.23,80.01 175.26,80.01 172.72,82.55 151.13,82.55 147.32,86.36 141.73,86.36 136.65,91.44 104.14,91.44
  pour Bottom: 104.14,46.99 205.74,46.99 205.74,91.44 104.14,91.44
N$1
  Top 0.203: J3.CONDUCTOR 44.58,21.59 44.45,21.72 D3.C
N$2
  Top 0.203: J6.CONDUCTOR 148.72,21.59 148.59,21.72 D6.C
N$3
  Top 0.203: R10.2 33.97,35.88 34.04,35.94 R11.1 33.91,35.94 33.27,35.31 IC3.6
N$4
  Top 0.203: R11.2 35.81,35.94 35.88,36.01 C8.1
N$5
  Top 0.203: SW1.C1 83.44,21.59 81.15,23.88 75.18,23.88 72.77,26.29 50.16,26.29 48.64,24.77 R17.1
N$6
  Top 0.203: R15.W 95.25,23.11 92.07,26.29 SW1.NO1
N$7
  Top 0.203: J1.CONDUCTOR R1.1
N$8
  Top 0.203: R9.2 30.1,31.88 30.35,32.13 IC3.5
N$9
  Top 0.203: Q1.3 57.78,6.35 58.67,7.24 59.44,7.24 59.56,7.37 | 59.56,7.37 R14.2 | Q2.1 59.63,7.3 59.56,7.37
N$10
  Top 0.203: J2.CONDUCTOR 8.89,23.75 9.27,24.13 | R4.1 12.32,30.86 9.27,27.81 9.27,24.13 | 9.27,24.13 R2.2
N$11
  Top 0.203: Q1.1 52.77,7.3 52.7,7.24 R13.1 52.7,9.78 53.34,10.41 R12.1
N$12  (via drill 0.71)
  Top 0.203: R16.2 58.74,10.48 60.2,11.94 60.45,11.94 60.96,12.45 | 60.96,12.45 C11.2 | 60.96,12.45 60.96,13.97 73.79,13.97 v75.44,15.62
  Bottom 0.203: SW1.C2 75.44,18.16 v75.44,15.62
N$13  (via drill 0.71)
  Top 0.203: R16.1 55.94,12.38 55.88,12.45 R18.2 v55.88,14.22
  Bottom 0.203: 55.88,19.3 D2.A v55.88,14.22
N$14
  Top 0.203: Q2.3 64.26,6.35 66.29,8.38 75.56,8.38 77.34,10.16 77.34,15.37 78.74,16.76 SW1.NC2
N$15
  Top 0.203: C11.1 63.44,10.48 63.5,10.54 | Q3.1 66.1,12.38 64.14,10.41 63.63,10.41 63.5,10.54 | 63.5,10.54 R19.2
N$16
  Top 0.203: AUDIO-.TP Q3.3
N$17
  Top 0.203: D1.1A 34.54,4.83 35.56,5.84 C1.2 37.15,5.78 38.99,3.94 IC1.1
N$18
  Top 0.203: C5.2 1.91,37.21 2.41,37.72 IC2.2
N$19
  Top 0.203: +28V.TP F1.1A
N$20
  Top 0.203: F1.2A 31.37,7.62 D1.2K
N$21  (via drill 0.71)
  Top 0.203: R6.2 20.64,38.8 20.7,38.86 C4.2 20.57,38.86 20.7,38.99 20.7,39.62 21.46,40.39 23.5,40.39 25.27,38.61 IC3.1 26.29,37.85 28.32,35.81 28.32,31.5 29.46,30.35 56.26,30.35 v58.8,27.81
  Bottom 0.203: R7.CW 64.77,18.16 63.75,19.18 63.75,22.86 v58.8,27.81
N$22
  Top 0.203: C4.1 22.48,38.86 22.54,38.8 R6.1 22.48,36.7 22.61,36.58 IC3.2 26.29,36.58 26.92,35.94 R3.2
N$23
  Top 0.203: R4.2 12.32,33.66 13.97,35.31 IC3.3
N$24  (via drill 0.71)
  Top 0.203: R10.1 56.9,33.66 v62.61,27.94
  Bottom 0.203: R7.W 67.31,23.24 v62.61,27.94
N$25  (via drill 0.71)
  Top 0.203: R8.2 66.55,30.42 v66.55,27.94
  Bottom 0.203: v66.55,27.94 66.93,27.94 70.36,24.51 70.36,19.68 69.85,19.18 R7.CCW 69.85,18.03
N$26
  Top 0.203: C5.1 1.91,35.31 2.03,35.18 IC2.4
N$27
  Top 0.203: C3.2 26.73,26.35 26.67,26.29 R1.2 26.67,26.42 26.92,26.67 R3.1
N$28
  Top 0.203: D3.A 44.58,24.89 44.7,24.77 R17.2
N$29  (via drill 0.71)
  Top 0.203: IC3.7 32.26,36.58 33.91,38.23 C8.2 33.97,39.43 v33.66,39.75 | SW1.NC1 83.44,16.89 81.15,19.18 76.83,19.18 72.9,15.24 v53.47,15.24 53.47,12.57 53.34,12.45 R12.2 53.34,12.32
  Bottom 0.203: v33.66,39.75 34.54,38.86 42.8,38.86 53.34,28.32 53.34,15.24 v53.47,15.24
N$30
  Top 0.203: R22.2 138.11,35.88 138.18,35.94 R21.1 138.05,35.94 137.41,35.31 IC5.6
N$31
  Top 0.203: R21.2 139.95,35.94 140.02,36.01 C13.1
N$32
  Top 0.203: SW2.C1 187.58,21.59 185.29,23.88 179.32,23.88 176.91,26.29 154.31,26.29 152.78,24.77 R20.1
N$33
  Top 0.203: R23.W 199.39,23.11 196.21,26.29 SW2.NO1
N$34
  Top 0.203: J5.CONDUCTOR R24.1
N$35
  Top 0.203: R25.2 134.24,31.88 134.49,32.13 IC5.5
N$36
  Top 0.203: J4.CONDUCTOR 113.03,23.75 113.41,24.13 | R32.1 116.46,30.86 113.41,27.81 113.41,24.13 | 113.41,24.13 R26.2
N$37
  Top 0.203: Q4.3 161.93,6.35 162.81,7.24 163.58,7.24 163.7,7.37 | 163.7,7.37 R28.2 | Q5.1 163.77,7.3 163.7,7.37
N$38
  Top 0.203: Q4.1 156.91,7.3 156.84,7.24 R37.1 156.84,9.78 157.48,10.41 R27.1
N$39  (via drill 0.71)
  Top 0.203: R29.2 162.88,10.48 164.34,11.94 164.59,11.94 165.1,12.45 | 165.1,12.45 C14.2 | 165.1,12.45 165.1,13.97 177.93,13.97 v179.58,15.62
  Bottom 0.203: SW2.C2 179.58,18.16 v179.58,15.62
N$40  (via drill 0.71)
  Top 0.203: R29.1 160.08,12.38 160.02,12.45 R33.2 v160.02,14.22
  Bottom 0.203: 160.02,19.3 D4.A v160.02,14.22
N$41
  Top 0.203: C14.1 167.58,10.48 167.64,10.54 | Q6.1 170.24,12.38 168.28,10.41 167.77,10.41 167.64,10.54 | 167.64,10.54 R30.2
N$42
  Top 0.203: D5.1A 138.68,4.83 139.7,5.84 C16.2 141.29,5.78 143.13,3.94 IC4.1
N$43
  Top 0.203: F2.2A 135.51,7.62 D5.2K
N$44
  Top 0.203: +28V1.TP F2.1A
N$45
  Top 0.203: Q5.3 168.4,6.35 170.43,8.38 179.71,8.38 181.48,10.16 181.48,15.37 182.88,16.76 SW2.NC2
N$46
  Top 0.203: AUDIO-1.TP Q6.3
N$47
  Top 0.203: C18.2 106.05,37.21 106.55,37.72 IC6.2
N$48
  Top 0.203: C18.1 106.05,35.31 106.17,35.18 IC6.4
N$49
  Top 0.203: C15.2 130.87,26.35 130.81,26.29 R24.2 130.81,26.42 131.06,26.67 R35.1
N$50  (via drill 0.71)
  Top 0.203: R36.2 124.78,38.8 124.84,38.86 C22.2 124.71,38.86 124.84,38.99 124.84,39.62 125.6,40.39 127.64,40.39 129.41,38.61 IC5.1 130.43,37.85 132.46,35.81 132.46,31.5 133.6,30.35 160.4,30.35 v162.94,27.81
  Bottom 0.203: R34.CW 168.91,18.16 167.89,19.18 167.89,22.86 v162.94,27.81
N$51
  Top 0.203: C22.1 126.62,38.86 126.68,38.8 R36.1 126.62,36.7 126.75,36.58 IC5.2 130.43,36.58 131.06,35.94 R35.2
N$52
  Top 0.203: D6.A 148.72,24.89 148.84,24.77 R20.2
N$53
  Top 0.203: R32.2 116.46,33.66 118.11,35.31 IC5.3
N$54  (via drill 0.71)
  Top 0.203: R22.1 161.04,33.66 v166.75,27.94
  Bottom 0.203: R34.W 171.45,23.24 v166.75,27.94
N$55  (via drill 0.71)
  Top 0.203: R38.2 170.69,30.42 v170.69,27.94
  Bottom 0.203: v170.69,27.94 171.07,27.94 174.5,24.51 174.5,19.68 173.99,19.18 R34.CCW 173.99,18.03
N$56  (via drill 0.71)
  Top 0.203: IC5.7 136.4,36.58 138.05,38.23 C13.2 138.11,39.43 v137.79,39.75 | SW2.NC1 187.58,16.89 185.29,19.18 180.97,19.18 177.04,15.24 v157.61,15.24 157.61,12.57 157.48,12.45 R27.2 157.48,12.32
  Bottom 0.203: v137.79,39.75 138.68,38.86 146.94,38.86 157.48,28.32 157.48,15.24 v157.61,15.24
N$57
  Top 0.203: J9.CONDUCTOR 44.58,68.58 44.45,68.71 D9.C
N$58
  Top 0.203: R41.2 33.97,82.87 34.04,82.93 R40.1 33.91,82.93 33.27,82.3 IC8.6
N$59
  Top 0.203: R40.2 35.81,82.93 35.88,83 C24.1
N$60
  Top 0.203: SW3.C1 83.44,68.58 81.15,70.87 75.18,70.87 72.77,73.28 50.16,73.28 48.64,71.75 R39.1
N$61
  Top 0.203: R42.W 95.25,70.1 92.07,73.28 SW3.NO1
N$62
  Top 0.203: J8.CONDUCTOR R43.1
N$63
  Top 0.203: R44.2 30.1,78.87 30.35,79.12 IC8.5
N$64
  Top 0.203: J7.CONDUCTOR 8.89,70.74 9.27,71.12 | R51.1 12.32,77.85 9.27,74.8 9.27,71.12 | 9.27,71.12 R45.2
N$65
  Top 0.203: Q7.3 57.78,53.34 58.67,54.23 59.44,54.23 59.56,54.36 | 59.56,54.36 R47.2 | Q8.1 59.63,54.29 59.56,54.36
N$66
  Top 0.203: Q7.1 52.77,54.29 52.7,54.23 R56.1 52.7,56.77 53.34,57.4 R46.1
N$67  (via drill 0.71)
  Top 0.203: R48.2 58.74,57.47 60.2,58.93 60.45,58.93 60.96,59.44 | 60.96,59.44 C25.2 | 60.96,59.44 60.96,60.96 73.79,60.96 v75.44,62.61
  Bottom 0.203: SW3.C2 75.44,65.15 v75.44,62.61
N$68  (via drill 0.71)
  Top 0.203: R48.1 55.94,59.37 55.88,59.44 R52.2 v55.88,61.21
  Bottom 0.203: 55.88,66.29 D7.A v55.88,61.21
N$69
  Top 0.203: C25.1 63.44,57.47 63.5,57.53 | Q9.1 66.1,59.37 64.14,57.4 63.63,57.4 63.5,57.53 | 63.5,57.53 R49.2
N$70
  Top 0.203: D8.1A 34.54,51.82 35.56,52.83 C27.2 37.15,52.77 38.99,50.93 IC7.1
N$71
  Top 0.203: F3.2A 31.37,54.61 D8.2K
N$72
  Top 0.203: +28V2.TP F3.1A
N$73
  Top 0.203: Q8.3 64.26,53.34 66.29,55.37 75.56,55.37 77.34,57.15 77.34,62.36 78.74,63.75 SW3.NC2
N$74
  Top 0.203: AUDIO-2.TP Q9.3
N$75
  Top 0.203: C29.2 1.91,84.2 2.41,84.71 IC9.2
N$76
  Top 0.203: C29.1 1.91,82.3 2.03,82.17 IC9.4
N$77
  Top 0.203: C26.2 26.73,73.34 26.67,73.28 R43.2 26.67,73.41 26.92,73.66 R54.1
N$78  (via drill 0.71)
  Top 0.203: R55.2 20.64,85.79 20.7,85.85 C33.2 20.57,85.85 20.7,85.98 20.7,86.61 21.46,87.38 23.5,87.38 25.27,85.6 IC8.1 26.29,84.84 28.32,82.8 28.32,78.49 29.46,77.34 56.26,77.34 v58.8,74.8
  Bottom 0.203: R53.CW 64.77,65.15 63.75,66.17 63.75,69.85 v58.8,74.8
N$79
  Top 0.203: C33.1 22.48,85.85 22.54,85.79 R55.1 22.48,83.69 22.61,83.57 IC8.2 26.29,83.57 26.92,82.93 R54.2
N$80
  Top 0.203: D9.A 44.58,71.88 44.7,71.75 R39.2
N$81
  Top 0.203: R51.2 12.32,80.64 13.97,82.3 IC8.3
N$82  (via drill 0.71)
  Top 0.203: R41.1 56.9,80.64 v62.61,74.93
  Bottom 0.203: R53.W 67.31,70.23 v62.61,74.93
N$83  (via drill 0.71)
  Top 0.203: R57.2 66.55,77.41 v66.55,74.93
  Bottom 0.203: v66.55,74.93 66.93,74.93 70.36,71.5 70.36,66.67 69.85,66.17 R53.CCW 69.85,65.02
N$84  (via drill 0.71)
  Top 0.203: IC8.7 32.26,83.57 33.91,85.22 C24.2 33.97,86.42 v33.66,86.74 | SW3.NC1 83.44,63.88 81.15,66.17 76.83,66.17 72.9,62.23 v53.47,62.23 53.47,59.56 53.34,59.44 R46.2 53.34,59.31
  Bottom 0.203: v33.66,86.74 34.54,85.85 42.8,85.85 53.34,75.31 53.34,62.23 v53.47,62.23
N$85
  Top 0.203: J12.CONDUCTOR 148.72,68.58 148.59,68.71 D12.C
N$86
  Top 0.203: R60.2 138.11,82.87 138.18,82.93 R59.1 138.05,82.93 137.41,82.3 IC11.6
N$87
  Top 0.203: R59.2 139.95,82.93 140.02,83 C35.1
N$88
  Top 0.203: SW4.C1 187.58,68.58 185.29,70.87 179.32,70.87 176.91,73.28 154.31,73.28 152.78,71.75 R58.1
N$89
  Top 0.203: R61.W 199.39,70.1 196.21,73.28 SW4.NO1
N$90
  Top 0.203: J11.CONDUCTOR R62.1
N$91
  Top 0.203: R63.2 134.24,78.87 134.49,79.12 IC11.5
N$92
  Top 0.203: J10.CONDUCTOR 113.03,70.74 113.41,71.12 | R70.1 116.46,77.85 113.41,74.8 113.41,71.12 | 113.41,71.12 R64.2
N$93
  Top 0.203: Q10.3 161.93,53.34 162.81,54.23 163.58,54.23 163.7,54.36 | 163.7,54.36 R66.2 | Q11.1 163.77,54.29 163.7,54.36
N$94
  Top 0.203: Q10.1 156.91,54.29 156.84,54.23 R75.1 156.84,56.77 157.48,57.4 R65.1
N$95  (via drill 0.71)
  Top 0.203: R67.2 162.88,57.47 164.34,58.93 164.59,58.93 165.1,59.44 | 165.1,59.44 C36.2 | 165.1,59.44 165.1,60.96 177.93,60.96 v179.58,62.61
  Bottom 0.203: SW4.C2 179.58,65.15 v179.58,62.61
N$96  (via drill 0.71)
  Top 0.203: R67.1 160.08,59.37 160.02,59.44 R71.2 v160.02,61.21
  Bottom 0.203: 160.02,66.29 D10.A v160.02,61.21
N$97
  Top 0.203: C36.1 167.58,57.47 167.64,57.53 | Q12.1 170.24,59.37 168.28,57.4 167.77,57.4 167.64,57.53 | 167.64,57.53 R68.2
N$98
  Top 0.203: D11.1A 138.68,51.82 139.7,52.83 C38.2 141.29,52.77 143.13,50.93 IC10.1
N$99
  Top 0.203: F4.2A 135.51,54.61 D11.2K
N$100
  Top 0.203: +28V3.TP F4.1A
N$101
  Top 0.203: Q11.3 168.4,53.34 170.43,55.37 179.71,55.37 181.48,57.15 181.48,62.36 182.88,63.75 SW4.NC2
N$102
  Top 0.203: AUDIO-3.TP Q12.3
N$103
  Top 0.203: C40.2 106.05,84.2 106.55,84.71 IC12.2
N$104
  Top 0.203: C40.1 106.05,82.3 106.17,82.17 IC12.4
N$105
  Top 0.203: C37.2 130.87,73.34 130.81,73.28 R62.2 130.81,73.41 131.06,73.66 R73.1
N$106  (via drill 0.71)
  Top 0.203: R74.2 124.78,85.79 124.84,85.85 C44.2 124.71,85.85 124.84,85.98 124.84,86.61 125.6,87.38 127.64,87.38 129.41,85.6 IC11.1 130.43,84.84 132.46,82.8 132.46,78.49 133.6,77.34 160.4,77.34 v162.94,74.8
  Bottom 0.203: R72.CW 168.91,65.15 167.89,66.17 167.89,69.85 v162.94,74.8
N$107
  Top 0.203: C44.1 126.62,85.85 126.68,85.79 R74.1 126.62,83.69 126.75,83.57 IC11.2 130.43,83.57 131.06,82.93 R73.2
N$108
  Top 0.203: D12.A 148.72,71.88 148.84,71.75 R58.2
N$109
  Top 0.203: R70.2 116.46,80.64 118.11,82.3 IC11.3
N$110  (via drill 0.71)
  Top 0.203: R60.1 161.04,80.64 v166.75,74.93
  Bottom 0.203: R72.W 171.45,70.23 v166.75,74.93
N$111  (via drill 0.71)
  Top 0.203: R76.2 170.69,77.41 v170.69,74.93
  Bottom 0.203: v170.69,74.93 171.07,74.93 174.5,71.5 174.5,66.67 173.99,66.17 R72.CCW 173.99,65.02
N$112  (via drill 0.71)
  Top 0.203: IC11.7 136.4,83.57 138.05,85.22 C35.2 138.11,86.42 v137.79,86.74 | SW4.NC1 187.58,63.88 185.29,66.17 180.97,66.17 177.04,62.23 v157.61,62.23 157.61,59.56 157.48,59.44 R65.2 157.48,59.31
  Bottom 0.203: v137.79,86.74 138.68,85.85 146.94,85.85 157.48,75.31 157.48,62.23 v157.61,62.23

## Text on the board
Top: ALPS - AOM Laser Power Stabilization | ALPS - AOM Laser Power Stabilization | University of Toronto - Physics | University of Toronto - Physics | J.Thywissen Labs | J.Thywissen Labs | Rev: C1 | Rev: C1 | A- | A- | A+ | A+ | 0.25A | 0.25A | ALPS - AOM Laser Power Stabilization | ALPS - AOM Laser Power Stabilization | University of Toronto - Physics | University of Toronto - Physics | J.Thywissen Labs | J.Thywissen Labs | Rev: C1 | Rev: C1 | A- | A- | A+ | A+ | 0.25A | 0.25A
Document: A. Stummer July'08 | C1 | 0.2mm(0.008") | 0.2mm(0.008") | 0.2mm(0.008") | 0.125mm(0.005") | 0.125mm(0.005") | Following are misc parts: | C1 Aug'08 A.Stummer Spin, again. | B2 Aug'08 A.Stummer As assembled on Rev:B1 PCB. | B1 July'08 A.Stummer Redesign. | A2 July'08 A.Stummer As assembled on Rev:A1 PCB. | A1 June'08 A.Stummer Initial design on Rev:A1 PCB.
Text: ALPS - AOM Laser | Power Stabilization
